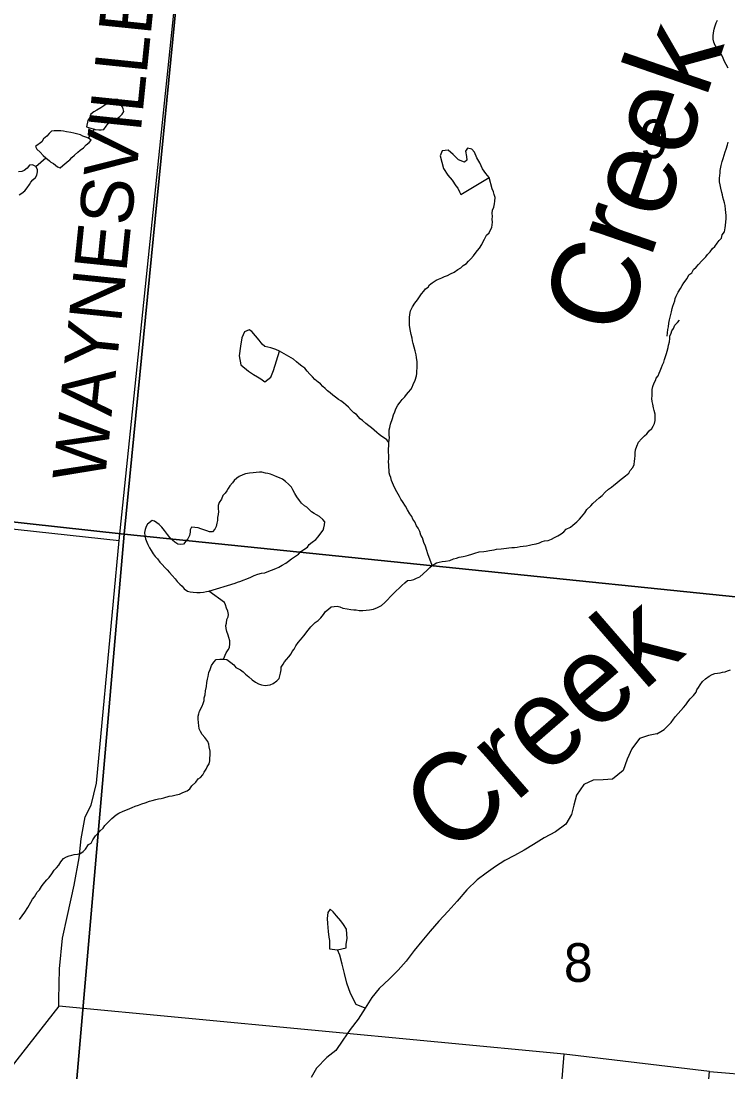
# Model space of a CAD drawing. Extents: x 1310247 to 1664935, y 284496 to 704931.
# Drawn here: x 1505539 to 1509578, y 505731 to 511730 of the extents above; entities that cross this region are included whole.
import ezdxf

# ---------------------------------------------------------------- set-up
doc = ezdxf.new("R2010")
doc.units = 0
for name, color, linetype in [('GM_X_County', 7, 'Continuous'), ('GM_X_County_Subdivision_Text', 7, 'Continuous'), ('GM_X_Interstate_Shield', 7, 'Continuous'), ('GM_X_Minor_Lake_Text', 7, 'Continuous'), ('GM_X_Minor_River', 7, 'Continuous'), ('GM_X_Minor_River_Text', 7, 'Continuous'), ('GM_X_Township_Subdivision', 7, 'Continuous'), ('GM_X_US_Location', 7, 'Continuous')]:
    doc.layers.add(name, color=color, linetype=linetype)

msp = doc.modelspace()

# ---------------------------------------------------------------- linework, layer by layer
at = {"layer": 'GM_X_County'}
for points in [[(1501457.6, 514459.3), (1506637.6, 513990.6), (1506128.6, 508801.3), (1500914.6, 509372.6)], [(1512143.7, 513477.1), (1511701, 508230.1), (1506128.6, 508801.3), (1506637.6, 513990.6)], [(1500914.6, 509372.6), (1506128.6, 508801.3), (1505662.2, 503437.3), (1500316.1, 503893.5)], [(1506128.6, 508801.3), (1511701, 508230.1), (1511191.1, 502926), (1505662.2, 503437.3)]]:
    msp.add_lwpolyline(points, close=True, dxfattribs=at)
at = {"layer": 'GM_X_County_Subdivision_Text'}
for points in [[(1505755.1, 506134.6), (1505755.2, 506143.9), (1505758.3, 506319.4), (1505775.4, 506493.8), (1505803.8, 506623.8), (1505843, 506797.7), (1505871.9, 506953.8), (1505881.8, 507062), (1505906.1, 507188.1), (1505939.4, 507253.7), (1505969.7, 507379.7), (1506100.4, 508764.4), (1506638.7, 513961.6), (1506648.1, 514089.2)], [(1502061.4, 509213.1), (1502095.3, 509209.3), (1503964.4, 508997.2), (1506100.4, 508764.4)], [(1508982.1, 503288.1), (1508789.5, 503391.3), (1508698.2, 503458.8), (1508602.9, 503542.2), (1508535.4, 503615.7), (1508479.9, 503675.2), (1508458, 503728.8), (1508459, 503797.3), (1508567.2, 504922.8), (1508641, 505832.6), (1505754.6, 506106.7), (1505755.1, 506134.6)], [(1505754.6, 506106.7), (1505306.6, 505538.2), (1505173.3, 505363.6)], [(1509472.4, 505734.1), (1508641, 505832.6)]]:
    msp.add_lwpolyline(points, dxfattribs=at)
at = {"layer": 'GM_X_Interstate_Shield'}
msp.add_lwpolyline([(1509436.3, 505322.4), (1509472.4, 505734.1), (1509744.1, 505711.4)], dxfattribs=at)
at = {"layer": 'GM_X_Minor_River'}
msp.add_line((1506287.4, 508879.1), (1506260.6, 508857.9), dxfattribs=at)
for points in [[(1505959.4, 511112.2), (1505963.4, 511111), (1505983.4, 511108.4), (1505997.4, 511108), (1506011.6, 511111.6), (1506026.2, 511129.1), (1506036.8, 511144.8), (1506053.3, 511158.4), (1506067.6, 511165.9), (1506088, 511173.3), (1506104.4, 511184.8), (1506116.9, 511198.5), (1506125.5, 511214.2), (1506122, 511228.4), (1506116.4, 511242.6), (1506102.9, 511261), (1506091.6, 511281.4), (1506073.5, 511282), (1506059.2, 511276.4), (1506036.7, 511263.1), (1506018.2, 511249.6), (1505995.6, 511234.3), (1505973, 511220.9), (1505954.6, 511211.5), (1505938.1, 511198), (1505931.5, 511180.2), (1505920.9, 511162.5), (1505913.6, 511126.6)], [(1505813, 510933.5), (1505817, 510937.2), (1505829.5, 510950.9), (1505844, 510964.5), (1505862.6, 510981.9), (1505877.1, 510993.5), (1505895.6, 511007), (1505910.2, 511022.5), (1505928.7, 511036), (1505939.2, 511049.7), (1505923.6, 511062.2), (1505909.6, 511066.6), (1505891.8, 511073.2), (1505877.9, 511079.6), (1505864, 511084.1), (1505840.1, 511090.8), (1505824.1, 511093.3), (1505798.2, 511098.1), (1505782.2, 511100.6), (1505766.2, 511103.1), (1505746.1, 511103.7), (1505728, 511102.3), (1505713.9, 511100.7), (1505699.4, 511087.1), (1505686.8, 511073.5), (1505668.3, 511058), (1505657.6, 511040.3), (1505622.6, 511013.4)], [(1505913.6, 511126.6), (1505929.5, 511120.1), (1505959.4, 511112.2)], [(1505622.6, 511013.4), (1505630.1, 510999.1), (1505647.6, 510980.5), (1505665.1, 510962), (1505680.7, 510949.5), (1505702.1, 510931.9)], [(1505529.1, 510737.8), (1505543.4, 510747.3), (1505560, 510760.9), (1505574.6, 510778.5), (1505587.3, 510796.1), (1505595.7, 510809.8), (1505606.3, 510823.5), (1505620.8, 510837.1), (1505629.3, 510850.9), (1505633.9, 510868.8), (1505632.3, 510882.8), (1505622.8, 510899.2), (1505605.1, 510909.7), (1505586.9, 510906.3), (1505574.3, 510890.6), (1505557.8, 510877.1), (1505543.5, 510871.6), (1505525.4, 510870.1)], [(1505702.1, 510931.9), (1505710.1, 510924.5), (1505723.8, 510916.1), (1505747.3, 510897.3), (1505763.3, 510892.8), (1505777.7, 510904.4), (1505813, 510933.5)], [(1506892.2, 508571.9), (1506912.4, 508577.3), (1506932.6, 508580.7), (1506955, 508590), (1506969.3, 508595.6), (1506993.7, 508604.8), (1507012, 508612.3), (1507030.5, 508623.8), (1507051, 508635.1), (1507067.4, 508646.6), (1507083.9, 508660.2), (1507106.6, 508675.5), (1507125, 508687), (1507137.6, 508702.6), (1507154, 508714.1), (1507174.6, 508727.5), (1507185.1, 508741.2), (1507201.6, 508754.7), (1507222.2, 508770.1), (1507236.8, 508785.7), (1507251.6, 508807.3), (1507264.1, 508822.9), (1507268.6, 508836.8), (1507273.2, 508854.7), (1507273.7, 508870.7), (1507262.2, 508885.1), (1507244.6, 508901.6), (1507226.8, 508910.2), (1507213, 508918.6), (1507199.3, 508929.1), (1507185.7, 508941.5), (1507172, 508954), (1507158.2, 508962.4), (1507140.6, 508977), (1507129.1, 508993.4), (1507113.7, 509013.9), (1507102.3, 509032.3), (1507090.9, 509054.6), (1507083.4, 509068.9), (1507067.8, 509085.4), (1507050.3, 509102), (1507032.7, 509114.6), (1507014.8, 509123.1), (1507000.9, 509127.5), (1506983.1, 509136.1), (1506963.3, 509142.7), (1506949.3, 509147.2), (1506935.3, 509149.6), (1506915.4, 509154.2), (1506901.4, 509154.7), (1506883.2, 509153.2), (1506865.1, 509151.8), (1506844.9, 509148.4), (1506820.7, 509145.1), (1506806.4, 509139.6), (1506786, 509130.2), (1506771.6, 509120.6), (1506757.1, 509107), (1506746.6, 509093.3), (1506732, 509075.8), (1506721.5, 509062), (1506715, 509048.2), (1506704.5, 509034.5), (1506692, 509020.9), (1506683.3, 509001.1), (1506670.6, 508981.5), (1506666, 508963.6), (1506665.4, 508945.6), (1506666.9, 508929.5), (1506664.3, 508913.5), (1506661.7, 508895.6), (1506661.2, 508879.6), (1506656.7, 508863.7), (1506654, 508843.8), (1506645.5, 508830), (1506632.9, 508814.3), (1506614.9, 508814.9), (1506600.9, 508819.3), (1506583.1, 508825.9), (1506567.1, 508830.4), (1506551.3, 508836.9), (1506531.3, 508839.5), (1506513.2, 508840.1), (1506504.7, 508826.3), (1506504.3, 508812.3), (1506501.6, 508792.3), (1506491, 508774.6), (1506480.5, 508760.9), (1506467.8, 508743.3), (1506449.7, 508741.9), (1506435.7, 508744.3), (1506418, 508754.9), (1506404.3, 508767.3), (1506388.7, 508781.8), (1506375.2, 508798.3), (1506357.9, 508820.8), (1506342.5, 508841.3), (1506328.9, 508855.8), (1506315.2, 508866.2), (1506301.4, 508874.7), (1506287.4, 508879.1)], [(1506260.6, 508857.9), (1506254.1, 508844.1), (1506247.6, 508828.2), (1506245, 508810.3), (1506246.4, 508792.2), (1506249.8, 508774.1), (1506257.3, 508755.8), (1506262.8, 508741.6), (1506272.3, 508723.3), (1506281.8, 508707), (1506293.2, 508688.6), (1506304.8, 508674.2), (1506318.4, 508659.8), (1506331.8, 508641.3), (1506345.4, 508626.9), (1506360.9, 508610.4), (1506374.6, 508597.9), (1506388.1, 508581.5), (1506401.7, 508565), (1506419.1, 508546.5), (1506430.6, 508530.1), (1506446.2, 508515.6), (1506459.9, 508503.1), (1506471.5, 508488.7), (1506489.1, 508476.2), (1506505.1, 508471.7), (1506523.1, 508469.1), (1506543.1, 508468.5), (1506563.2, 508467.9), (1506581.3, 508469.3), (1506599.5, 508472.8), (1506612.1, 508475.5)], [(1506612.1, 508475.5), (1506761.9, 508521.8), (1506776.2, 508527.4), (1506794.4, 508532.9), (1506808.7, 508538.4), (1506829, 508545.8), (1506851.4, 508555.1), (1506871.8, 508564.5), (1506892.2, 508571.9)]]:
    msp.add_lwpolyline(points, dxfattribs=at)
at = {"layer": 'GM_X_Minor_River_Text'}
for points in [[(1509578.3, 511460.5), (1509566.7, 511482.8), (1509555.1, 511503.1), (1509547.5, 511523.3), (1509537.8, 511541.6), (1509526.1, 511555.8), (1509518.4, 511574.1), (1509504.7, 511590.4), (1509497.1, 511608.6), (1509493.5, 511626.8), (1509493.9, 511644.8), (1509494.3, 511662.9), (1509498.7, 511682.9), (1509503.1, 511696.9), (1509509.6, 511718.8), (1509518, 511734.8)], [(1505923.6, 511062.2), (1505959.4, 511112.2)], [(1509229.7, 509930.3), (1509232.1, 509950.3), (1509234.6, 509968.3), (1509236.9, 509984.4), (1509239.4, 510004.4), (1509243.9, 510024.4), (1509248.4, 510046.4), (1509255, 510070.4), (1509259.4, 510088.4), (1509261.7, 510102.4), (1509274.5, 510132.3), (1509276.8, 510146.3), (1509281.2, 510160.3), (1509293.7, 510182.2), (1509306.3, 510204), (1509316.7, 510219.9), (1509325.1, 510235.8), (1509343.8, 510259.6), (1509354.4, 510281.5), (1509370.7, 510293.2), (1509381.2, 510311.1), (1509395.6, 510324.9), (1509410.1, 510340.7), (1509428.6, 510360.5), (1509451.3, 510384.2), (1509459.7, 510398.1), (1509476.1, 510411.8), (1509488.6, 510431.7), (1509503, 510443.5), (1509515.4, 510461.3), (1509527.9, 510477.2), (1509540.3, 510491), (1509544.7, 510509), (1509557.2, 510526.9), (1509561.7, 510548.9), (1509564, 510562.9), (1509564.5, 510583), (1509566.9, 510601), (1509567.3, 510619.1), (1509565.7, 510637.2), (1509564.1, 510653.3), (1509560.6, 510677.5), (1509556.9, 510691.6), (1509553.2, 510705.7), (1509547.5, 510723.9), (1509545.9, 510738), (1509542.1, 510752.1), (1509536.6, 510776.3), (1509533, 510794.5), (1509529.4, 510812.6), (1509529.9, 510832.7), (1509530.2, 510848.7), (1509532.6, 510862.8), (1509532.9, 510876.8), (1509539.6, 510904.8), (1509544.1, 510928.8), (1509550.5, 510944.8), (1509555, 510964.8), (1509561.4, 510982.7), (1509567.8, 510998.7), (1509574.4, 511022.7), (1509578.8, 511038.7)], [(1508212.6, 510836.5), (1508195, 510859), (1508175.6, 510885.5), (1508160.3, 510920), (1508143, 510948.5), (1508129.7, 510980.9), (1508114.1, 510999.3), (1508090.1, 511003.9), (1508077.6, 510986.2), (1508082.9, 510956), (1508086.4, 510935.8), (1508072.1, 510924.2), (1508038.2, 510937), (1508006.8, 510967.9), (1507979.3, 510992.6), (1507945.1, 510989.4), (1507934.3, 510959.6), (1507952.7, 510889), (1507977.9, 510850.2), (1508001.3, 510821.6), (1508022.6, 510789), (1508034.3, 510776.7), (1508043.8, 510754.4), (1508051.5, 510740.1)], [(1505622.8, 510899.2), (1505680.7, 510949.5)], [(1508051.5, 510740.1), (1508212.6, 510836.5)], [(1508084, 510346.3), (1508094.5, 510360), (1508109, 510371.6), (1508123.6, 510389.2), (1508134.1, 510402.9), (1508146.8, 510420.5), (1508157.3, 510434.2), (1508172, 510453.8), (1508176.5, 510467.7), (1508187.1, 510485.4), (1508197.9, 510507.1), (1508212.4, 510520.7), (1508218.9, 510534.5), (1508229.5, 510552.2), (1508229.9, 510566.2), (1508232.5, 510582.2), (1508231, 510598.2), (1508231.5, 510614.3), (1508230.1, 510632.3), (1508232.7, 510650.3), (1508239.3, 510668.1), (1508244, 510686), (1508246.5, 510702), (1508247.1, 510722), (1508241.7, 510740.2), (1508238.2, 510754.3), (1508230.7, 510772.6), (1508212.6, 510836.5)], [(1507888.4, 508621.3), (1507862.5, 508688.2), (1507857.1, 508708.4), (1507849.9, 508732.7), (1507840.5, 508753), (1507833.3, 508779.3), (1507823.8, 508795.6), (1507816.5, 508815.9), (1507807, 508834.2), (1507797.4, 508848.5), (1507788.1, 508870.8), (1507776.6, 508887.2), (1507771.1, 508901.4), (1507759.5, 508917.8), (1507746.2, 508940.2), (1507734.8, 508960.6), (1507717.6, 508987.2), (1507708.1, 509001.5), (1507700.5, 509015.8), (1507685.3, 509042.3), (1507677.7, 509056.6), (1507666.5, 509081), (1507655.3, 509107.3), (1507651.8, 509123.5), (1507646.3, 509137.7), (1507642.7, 509151.8), (1507641.2, 509167.9), (1507639.7, 509182), (1507640.1, 509196), (1507638.7, 509214), (1507639.3, 509232.1), (1507639.9, 509250.1), (1507638.5, 509268.1), (1507639.1, 509286.2), (1507639.8, 509306.2), (1507640.4, 509324.2), (1507642.8, 509338.1), (1507643.3, 509352.1), (1507641.8, 509366.2), (1507642.2, 509380.2), (1507642.7, 509396.2), (1507645.2, 509410.2), (1507649.8, 509428.1), (1507661, 509461.8), (1507667.7, 509481.6), (1507674.3, 509499.5), (1507680.8, 509515.3), (1507691.6, 509537), (1507704.2, 509554.6), (1507716.8, 509570.3), (1507731.3, 509583.8), (1507741.8, 509597.5), (1507752.3, 509611.2), (1507764.9, 509626.9), (1507773.4, 509640.6), (1507779.9, 509654.5), (1507790.8, 509680.2), (1507797.6, 509704), (1507800, 509718), (1507800.5, 509732), (1507801.1, 509750), (1507801.7, 509768), (1507802.2, 509784), (1507799.1, 509810.2), (1507795.5, 509824.3), (1507790.2, 509846.5), (1507784.9, 509868.7), (1507779.6, 509888.9), (1507776.1, 509905), (1507772.5, 509919.2), (1507767.2, 509941.4), (1507762.2, 509969.6), (1507758.9, 509993.7), (1507757.7, 510015.8), (1507758.4, 510037.8), (1507760.9, 510053.8), (1507763.7, 510075.7), (1507774.5, 510099.4), (1507789.2, 510119), (1507803.9, 510138.6), (1507814.5, 510156.3), (1507827.1, 510171.9), (1507839.7, 510187.6), (1507850.2, 510201.3), (1507864.6, 510210.8), (1507873.1, 510224.6), (1507887.5, 510236.2), (1507910.1, 510251.5), (1507924.4, 510257.1), (1507942.7, 510264.5), (1507959, 510272), (1507975.3, 510277.6), (1507991.7, 510287.1), (1508014.1, 510296.4), (1508034.7, 510311.8), (1508051.1, 510321.3), (1508065.6, 510334.9), (1508084, 510346.3)], [(1508481.2, 508745.2), (1508501.5, 508750.6), (1508515.8, 508758.2), (1508530, 508761.8), (1508550.2, 508765.1), (1508568.5, 508772.6), (1508586.9, 508782), (1508605.3, 508791.5), (1508623.8, 508803), (1508640.2, 508814.5), (1508652.8, 508830.1), (1508677.3, 508841.4), (1508691.7, 508852.9), (1508714.4, 508870.3), (1508729, 508885.8), (1508741.5, 508899.5), (1508760.4, 508923), (1508771, 508940.7), (1508793.8, 508962), (1508806.3, 508975.6), (1508825, 508993.1), (1508841.6, 509008.6), (1508858.1, 509022.1), (1508876.7, 509039.6), (1508895.4, 509057), (1508911.8, 509068.5), (1508926.3, 509080.1), (1508942.8, 509093.6), (1508957.3, 509107.2), (1508975.9, 509120.7), (1508992.4, 509134.2), (1509011, 509149.6), (1509019.5, 509163.4), (1509034.1, 509181), (1509040.7, 509198.8), (1509043.3, 509216.8), (1509045.8, 509230.7), (1509046.5, 509250.7), (1509046.9, 509264.7), (1509049.5, 509282.7), (1509056.2, 509302.5), (1509067, 509326.2), (1509083.8, 509345.7), (1509100.3, 509361.2), (1509114.8, 509372.8), (1509127.4, 509390.5), (1509141.9, 509404), (1509150.4, 509417.8), (1509156.9, 509431.6), (1509161.5, 509449.5), (1509162.1, 509467.5), (1509160.7, 509485.6), (1509155.4, 509505.8), (1509151.9, 509522), (1509148.5, 509542.1), (1509145, 509558.2), (1509143.5, 509574.3), (1509144.1, 509590.3), (1509144.7, 509608.3), (1509145.3, 509626.3), (1509147.9, 509644.3), (1509156.6, 509664.1), (1509163.1, 509677.9), (1509167.5, 509691.8), (1509178, 509705.5), (1509184.5, 509719.3), (1509191, 509733.1), (1509197.7, 509753), (1509204.2, 509766.8), (1509210.7, 509782.6), (1509215.3, 509798.5), (1509219.8, 509814.4), (1509226.4, 509832.2), (1509230.9, 509846.1), (1509235.6, 509866), (1509238, 509879.9), (1509242.7, 509897.8), (1509245.3, 509917.8), (1509245.8, 509931.8), (1509252.3, 509947.6), (1509256.8, 509961.5), (1509267.3, 509975.2), (1509273.9, 509993), (1509288.5, 510008.6), (1509301, 510022.2)], [(1507015.3, 509844.8), (1506995.4, 509855.3), (1506965.5, 509864.1), (1506931.6, 509872.9), (1506915.8, 509885.3), (1506900.3, 509907.8), (1506878.8, 509932.3), (1506857.3, 509956.9), (1506841.5, 509967.4), (1506815.1, 509956), (1506800.2, 509922.2), (1506793, 509874.3), (1506785.6, 509818.3), (1506794.4, 509768), (1506837.7, 509730.8), (1506867.4, 509712), (1506889.2, 509699.5), (1506909, 509687)], [(1506909, 509687), (1506932.7, 509670.3), (1506965.5, 509697.6), (1506980.4, 509735.3), (1507015.3, 509844.8)], [(1507640.4, 509324.2), (1507628.8, 509338.6), (1507615.1, 509349), (1507599.3, 509357.5), (1507585.6, 509370), (1507571.9, 509380.4), (1507556.3, 509394.9), (1507540.6, 509407.4), (1507525, 509419.9), (1507509.3, 509432.4), (1507489.8, 509449), (1507476.1, 509459.5), (1507454.8, 509484.2), (1507441, 509492.6), (1507425.4, 509509.1), (1507409.9, 509525.6), (1507394.3, 509538.2), (1507380.6, 509550.6), (1507366.9, 509561), (1507353.1, 509569.5), (1507335.4, 509582), (1507319.8, 509594.5), (1507304.1, 509607), (1507290.4, 509619.5), (1507276.8, 509631.9), (1507263.1, 509644.4), (1507249.6, 509658.8), (1507235.8, 509669.3), (1507218.2, 509683.8), (1507204.6, 509698.3), (1507189.1, 509714.8), (1507173.6, 509731.3), (1507160.1, 509747.8), (1507142.4, 509760.3), (1507126.7, 509772.8), (1507113.1, 509785.3), (1507095.5, 509799.8), (1507015.3, 509844.8)], [(1506807.5, 508015.5), (1506821, 508001.1), (1506840.7, 507986.5), (1506860.2, 507969.8), (1506877.8, 507955.3), (1506895.6, 507946.7), (1506913.5, 507940.1), (1506933.5, 507937.5), (1506947.6, 507939.1), (1506961.7, 507940.7), (1506980, 507948.1), (1507000.6, 507963.5), (1507013.1, 507977.1), (1507017.7, 507993), (1507022.2, 508006.9), (1507024.8, 508026.9), (1507025.3, 508040.9), (1507035.9, 508058.6), (1507044.4, 508072.3), (1507054.9, 508086), (1507069.4, 508099.6), (1507082.1, 508117.3), (1507088.6, 508131.1), (1507099.1, 508144.8), (1507109.7, 508162.5), (1507122.4, 508182.1), (1507135, 508197.8), (1507153.8, 508221.2), (1507179, 508252.5), (1507193.7, 508272.1), (1507218.6, 508297.4), (1507237.1, 508308.8), (1507251.6, 508322.4), (1507266.3, 508342), (1507279, 508359.6), (1507295.5, 508373.1), (1507310, 508386.7), (1507328.1, 508388.2), (1507344.3, 508389.7), (1507360.2, 508385.2), (1507378, 508378.6), (1507402, 508373.8), (1507424, 508371.2), (1507440, 508368.7), (1507454.1, 508368.2), (1507470, 508365.7), (1507492.1, 508365.1), (1507510.3, 508366.5), (1507530.4, 508367.9), (1507552.7, 508373.2), (1507575.1, 508382.5), (1507597.6, 508393.8), (1507618.2, 508411.2), (1507632.8, 508426.8), (1507649.5, 508444.3), (1507666.1, 508461.9), (1507682.7, 508477.4), (1507699.3, 508492.9), (1507713.9, 508508.5), (1507732.5, 508523.9), (1507746.9, 508535.5), (1507767.1, 508538.9), (1507783.3, 508542.4), (1507797.6, 508550), (1507818, 508557.3), (1507836.6, 508574.8), (1507859.4, 508596.1), (1507873.9, 508609.7), (1507888.4, 508621.3), (1507913, 508636.6), (1507927.2, 508640.1), (1507945.5, 508645.6), (1507963.6, 508647), (1507987.8, 508650.3), (1508010.2, 508659.6), (1508026.4, 508663.1), (1508042.7, 508668.6), (1508064.9, 508674), (1508081.1, 508677.5), (1508095.3, 508681), (1508113.6, 508686.5), (1508131.8, 508691.9), (1508156.2, 508699.2), (1508182.4, 508702.4), (1508196.5, 508704), (1508214.7, 508707.4), (1508241, 508710.6), (1508255.1, 508714.2), (1508281.4, 508717.4), (1508297.5, 508718.9), (1508311.6, 508720.4), (1508325.7, 508722), (1508341.9, 508725.5), (1508358, 508725), (1508374.1, 508726.5), (1508390.3, 508730), (1508408.4, 508731.5), (1508426.6, 508734.9), (1508442.8, 508738.4), (1508459, 508741.9), (1508481.2, 508745.2)], [(1506695.3, 508087.1), (1506710.5, 508122.7), (1506723.2, 508140.4), (1506729.7, 508154.2), (1506732.3, 508174.1), (1506730.9, 508192.2), (1506725.5, 508210.4), (1506721.9, 508224.5), (1506714.6, 508244.8), (1506711.1, 508263), (1506709.7, 508279), (1506712.1, 508293), (1506714.8, 508312.9), (1506721.4, 508328.8), (1506723.8, 508342.7), (1506720.4, 508360.8), (1506713, 508379.1), (1506707.6, 508397.3), (1506702, 508411.5), (1506612.1, 508475.5)], [(1505630.6, 506757.6), (1505645.1, 506771.2), (1505655.8, 506788.9), (1505666.3, 506802.6), (1505687.2, 506828), (1505699.7, 506841.6), (1505714.4, 506861.2), (1505729.2, 506882.8), (1505741.7, 506896.4), (1505754.3, 506912), (1505766.9, 506929.7), (1505781.6, 506949.3), (1505798, 506958.8), (1505814.3, 506964.3), (1505828.5, 506967.9), (1505842.6, 506971.4), (1505860.8, 506974.9), (1505875, 506976.5), (1505893.5, 506989.9), (1505908, 507003.5), (1505924.9, 507029), (1505939.2, 507036.6), (1505949.9, 507056.3), (1505964.7, 507077.9), (1505977.2, 507091.5), (1505991.8, 507107.1), (1506008.4, 507122.6), (1506016.9, 507138.4), (1506037.6, 507155.8), (1506058.4, 507177.1), (1506083.2, 507198.4), (1506097.6, 507208), (1506122.1, 507219.3), (1506146.5, 507228.5), (1506173, 507239.7), (1506191.3, 507247.2), (1506209.7, 507254.6), (1506230, 507262), (1506248.3, 507267.5), (1506272.7, 507276.7), (1506288.9, 507280.2), (1506309.1, 507285.6), (1506325.3, 507289.1), (1506339.5, 507292.7), (1506355.7, 507296.2), (1506386.1, 507305.3), (1506402.3, 507306.8), (1506424.5, 507312.1), (1506444.8, 507317.5), (1506463.2, 507326.9), (1506487.6, 507336.2), (1506504.1, 507347.7), (1506514.7, 507363.4), (1506537.5, 507384.7), (1506550.2, 507404.4), (1506564.5, 507412), (1506577.1, 507427.6), (1506585.5, 507441.4), (1506596.2, 507459.1), (1506602.7, 507472.9), (1506613.3, 507490.6), (1506617.8, 507506.5), (1506618.3, 507520.5), (1506619, 507540.5), (1506619.7, 507562.5), (1506614.5, 507586.7), (1506611, 507602.9), (1506605.4, 507617.1), (1506588.1, 507639.6), (1506574.6, 507658.1), (1506565.1, 507674.4), (1506557.6, 507688.7), (1506554.2, 507708.8), (1506552.7, 507722.9), (1506551.4, 507747), (1506551.9, 507761), (1506554.4, 507774.9), (1506558.9, 507790.8), (1506573.9, 507818.4), (1506580.4, 507834.2), (1506585.1, 507852.1), (1506585.5, 507866.1), (1506590.1, 507884), (1506592.9, 507906), (1506597.7, 507931.9), (1506600.5, 507953.8), (1506605.1, 507973.7), (1506607.6, 507987.6), (1506612.4, 508011.5), (1506619, 508027.4), (1506627.8, 508051.1), (1506640.5, 508070.8), (1506653, 508084.4), (1506675.2, 508087.7), (1506695.3, 508087.1), (1506715.3, 508084.5), (1506736.9, 508067.8), (1506754.5, 508055.2), (1506766, 508038.9), (1506793.7, 508026), (1506807.5, 508015.5)], [(1509171.3, 507661.1), (1509194.8, 507675.2), (1509213.2, 507684.9), (1509225.6, 507698.7), (1509240, 507712.5), (1509252.4, 507726.4), (1509266.9, 507744.2), (1509277.3, 507760), (1509293.8, 507777.8), (1509308.2, 507793.6), (1509322.7, 507811.5), (1509337.2, 507827.2), (1509347.6, 507843.1), (1509362.1, 507860.9), (1509380.7, 507880.7), (1509395.1, 507898.5), (1509399.5, 507912.5), (1509409.9, 507926.3), (1509418.2, 507940.3), (1509432.8, 507960.1), (1509449.2, 507975.8), (1509469.7, 507989.5), (1509488, 507999.2), (1509502.2, 508005), (1509518.4, 508006.7), (1509532.5, 508008.5), (1509546.7, 508012.2), (1509560.8, 508014), (1509575, 508019.7), (1509591.3, 508025.5)], [(1509171.3, 507661.1), (1509123.1, 507651.7), (1509072.5, 507634.8), (1509028.9, 507575.7), (1509001.3, 507516.2), (1508979.7, 507452.6), (1508918.2, 507402), (1508863.9, 507399.3), (1508807.6, 507396.6), (1508754.7, 507371.8), (1508713.1, 507310.7), (1508697.6, 507252.9), (1508684.3, 507201.1), (1508650.8, 507145.7), (1508591.4, 507101), (1508528.3, 507066.5), (1508467.2, 507029.9), (1508414.1, 506997), (1508357.2, 506966.3), (1508302.2, 506937.6), (1508249.1, 506902.8), (1508196, 506866), (1508144.9, 506827.1), (1508085.2, 506770.4), (1508031.4, 506705.5), (1507979.8, 506648.6), (1507926.2, 506591.8), (1507876.6, 506534.8), (1507829, 506477.8), (1507785.5, 506424.7), (1507739.8, 506363.6), (1507694.4, 506312.6), (1507644.9, 506261.7), (1507585.3, 506207), (1507543.9, 506155.8), (1507504.3, 506094.6), (1507464.6, 506031.4), (1507418.9, 505972.4), (1507377.3, 505913.2), (1507337.7, 505854), (1507286.5, 505813.1), (1507226.8, 505752.4), (1507197.3, 505699)], [(1505531, 506600.4), (1505545.8, 506622), (1505560.6, 506643.5), (1505577.5, 506669.1), (1505586, 506682.8), (1505594.6, 506700.6), (1505605.2, 506716.3), (1505615.7, 506730), (1505630.6, 506757.6)], [(1507396.2, 506440.2), (1507396.7, 506460.2), (1507401.5, 506492.2), (1507400.1, 506518.3), (1507398.8, 506546.4), (1507381.4, 506572.9), (1507365.8, 506593.4), (1507340.4, 506622.1), (1507322.8, 506644.5), (1507305.2, 506661), (1507292.6, 506641.3), (1507287.8, 506607.3), (1507289.1, 506579.2), (1507294, 506532.9), (1507297.2, 506500.8), (1507300.8, 506480.6), (1507300.3, 506462.6), (1507301.6, 506434.5)], [(1507301.6, 506434.5), (1507347.7, 506427.3), (1507396.2, 506440.2)], [(1507504.3, 506094.6), (1507452.6, 506115.9), (1507422, 506178.9), (1507399.3, 506237.6), (1507386.6, 506292), (1507373.8, 506346.5), (1507361, 506396.9), (1507347.7, 506427.3)]]:
    msp.add_lwpolyline(points, dxfattribs=at)

# ---------------------------------------------------------------- texts
at = {"layer": 'GM_X_Minor_Lake_Text'}
for height, rotation, p in [(499.98, 70.94734, (1508976.6, 509911.7)), (499.99, 40.94862, (1507996.7, 506948.7))]:
    msp.add_text('Creek', height=height, rotation=rotation, dxfattribs=at).set_placement(p)
at = {"layer": 'GM_X_Township_Subdivision'}
msp.add_text('WAYNESVILLE', height=300, rotation=84.12672, dxfattribs=at).set_placement((1506016.7, 509092.6))
at = {"layer": 'GM_X_US_Location'}
for s, p in [('9', (1509073.4, 510946.5)), ('8', (1508640, 506245.1))]:
    msp.add_text(s, height=221, rotation=0.00001, dxfattribs=at).set_placement(p)

doc.saveas('drawing.dxf')
